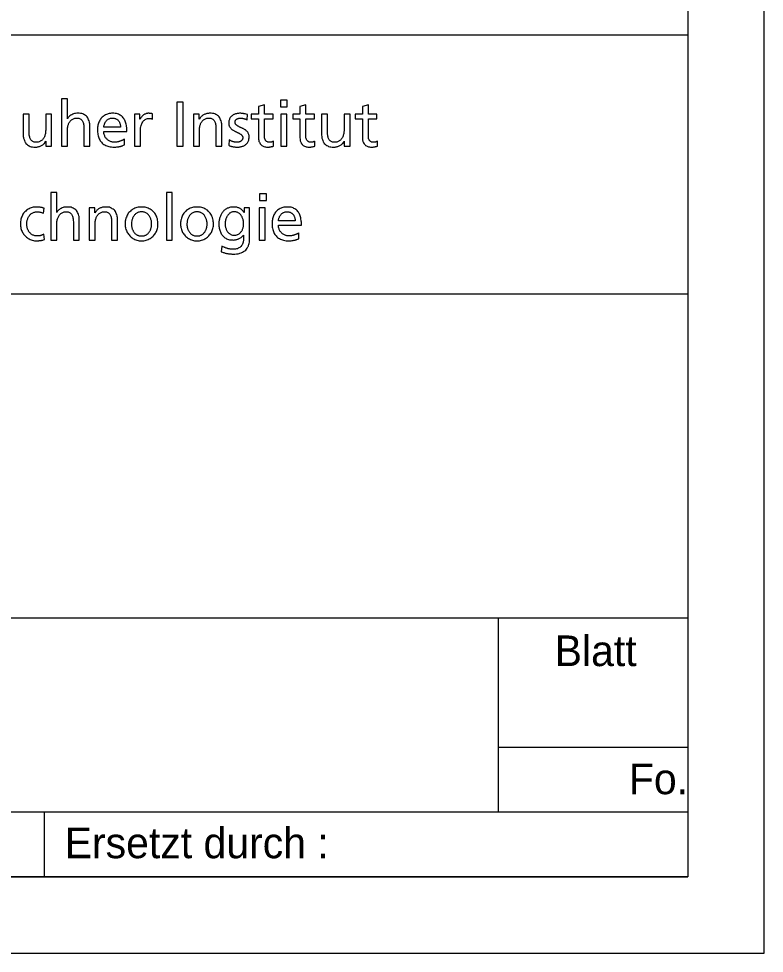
# Model space of a CAD drawing. Extents: x 0 to 297, y 0 to 210.
# Drawn here: x 272.66 to 297, y 0 to 30.52 of the extents above; entities that cross this region are included whole.
import ezdxf

# ---------------------------------------------------------------- set-up
doc = ezdxf.new("R2010")
doc.units = 0
doc.layers.add('90_Plankopf', color=7, linetype='Continuous')

msp = doc.modelspace()

# ---------------------------------------------------------------- linework, layer by layer
at = {"layer": '90_Plankopf'}
for p, q in [((294.5, 42.495), (294.5, 2.5)), ((205.56, 29.995), (294.5, 29.995)), ((205.56, 29.995), (294.5, 29.995)), ((294.5, 29.995), (294.5, 2.5)), ((277.028, 27.242), (277.028, 27.416)), ((280.116, 27.22), (280.133, 27.389)), ((275.986, 26.98), (275.441, 26.98)), ((275.441, 26.836), (276.193, 26.836)), ((276.112, 26.396), (276.112, 26.59)), ((279.536, 26.559), (279.526, 26.386)), ((280.981, 26.357), (280.981, 26.522)), ((282.333, 26.357), (282.333, 26.522)), ((284.372, 26.357), (284.372, 26.522)), ((273.476, 24.168), (273.492, 24.329)), ((281.686, 23.92), (281.142, 23.92)), ((281.142, 23.776), (281.893, 23.776)), ((281.812, 23.337), (281.812, 23.53)), ((273.5, 23.312), (273.486, 23.485)), ((279.298, 23.087), (279.277, 22.907)), ((252.501, 21.535), (294.5, 21.535)), ((252.501, 10.96), (294.5, 10.96)), ((288.324, 4.615), (288.324, 10.96)), ((288.324, 6.73), (294.5, 6.73)), ((252.501, 4.615), (294.5, 4.615)), ((273.5, 2.5), (273.5, 4.615)), ((294.5, 2.5), (205.56, 2.5)), ((211.4, 2.5), (294.5, 2.5)), ((211.4, 2.5), (294.5, 2.5))]:
    msp.add_line(p, q, dxfattribs=at)
for points in [[(0, 0), (297, 0), (297, 210), (0, 210)], [(12.5, 207.5), (294.5, 207.5), (294.5, 2.5), (12.5, 2.5)]]:
    msp.add_lwpolyline(points, close=True, dxfattribs=at)
for points in [[(274.255, 27.255), (274.251, 27.255), (274.251, 27.9), (274.057, 27.9), (274.057, 26.353), (274.251, 26.353), (274.251, 26.84)], [(277.823, 26.353), (278.029, 26.353), (278.029, 27.793), (277.823, 27.793), (277.823, 26.353)], [(281.427, 27.64), (281.427, 27.859), (281.208, 27.859), (281.208, 27.64), (281.427, 27.64)], [(280.686, 26.673), (280.686, 27.248), (280.964, 27.248), (280.964, 27.405), (280.686, 27.405), (280.686, 27.711), (280.492, 27.649), (280.492, 27.405), (280.254, 27.405), (280.254, 27.248), (280.492, 27.248), (280.492, 26.633)], [(282.038, 26.673), (282.038, 27.248), (282.316, 27.248), (282.316, 27.405), (282.038, 27.405), (282.038, 27.711), (281.844, 27.649), (281.844, 27.405), (281.606, 27.405), (281.606, 27.248), (281.844, 27.248), (281.844, 26.633)], [(284.077, 26.673), (284.077, 27.248), (284.355, 27.248), (284.355, 27.405), (284.077, 27.405), (284.077, 27.711), (283.883, 27.649), (283.883, 27.405), (283.646, 27.405), (283.646, 27.248), (283.883, 27.248), (283.883, 26.633)], [(273.002, 26.86), (273.002, 27.405), (272.808, 27.405), (272.808, 26.78)], [(273.547, 26.52), (273.551, 26.52), (273.551, 26.353), (273.739, 26.353), (273.739, 27.405), (273.545, 27.405), (273.545, 26.918)], [(276.626, 27.242), (276.622, 27.242), (276.622, 27.405), (276.44, 27.405), (276.44, 26.353), (276.634, 26.353), (276.634, 26.832)], [(278.558, 27.238), (278.554, 27.238), (278.554, 27.405), (278.366, 27.405), (278.366, 26.353), (278.56, 26.353), (278.56, 26.84)], [(281.22, 27.405), (281.22, 26.353), (281.414, 26.353), (281.414, 27.405), (281.22, 27.405)], [(282.742, 26.86), (282.742, 27.405), (282.548, 27.405), (282.548, 26.78)], [(283.286, 26.52), (283.29, 26.52), (283.29, 26.353), (283.478, 26.353), (283.478, 27.405), (283.284, 27.405), (283.284, 26.918)], [(274.793, 26.898), (274.793, 26.353), (274.987, 26.353), (274.987, 26.978)], [(279.103, 26.898), (279.103, 26.353), (279.297, 26.353), (279.297, 26.978)], [(273.909, 24.195), (273.905, 24.195), (273.905, 24.841), (273.711, 24.841), (273.711, 23.293), (273.905, 23.293), (273.905, 23.78)], [(277.482, 23.293), (277.676, 23.293), (277.676, 24.841), (277.482, 24.841), (277.482, 23.293)], [(280.747, 24.581), (280.747, 24.799), (280.528, 24.799), (280.528, 24.581), (280.747, 24.581)], [(275.152, 24.178), (275.147, 24.178), (275.147, 24.346), (274.96, 24.346), (274.96, 23.293), (275.154, 23.293), (275.154, 23.78)], [(280.198, 23.339), (280.198, 24.346), (280.018, 24.346), (280.018, 24.189), (280.014, 24.189)], [(280.515, 24.346), (280.515, 23.293), (280.709, 23.293), (280.709, 24.346), (280.515, 24.346)], [(274.448, 23.838), (274.448, 23.293), (274.642, 23.293), (274.642, 23.918)], [(275.696, 23.838), (275.696, 23.293), (275.89, 23.293), (275.89, 23.918)], [(280, 23.456), (280.004, 23.456), (280.004, 23.353)]]:
    msp.add_lwpolyline(points, dxfattribs=at)
for points in [[(274.251, 26.84), (274.251, 26.904), (274.257, 26.963), (274.27, 27.016), (274.282, 27.069), (274.302, 27.114), (274.328, 27.152), (274.354, 27.191), (274.387, 27.221), (274.427, 27.242), (274.468, 27.262), (274.515, 27.273), (274.571, 27.273), (274.627, 27.27), (274.671, 27.254), (274.704, 27.226), (274.736, 27.198), (274.759, 27.156), (274.773, 27.102), (274.787, 27.048), (274.794, 26.979), (274.793, 26.898)], [(274.987, 26.978), (274.988, 27.073), (274.974, 27.154), (274.946, 27.221), (274.918, 27.288), (274.874, 27.34), (274.816, 27.376), (274.758, 27.412), (274.684, 27.43), (274.593, 27.43), (274.519, 27.43), (274.454, 27.414), (274.395, 27.384), (274.337, 27.354), (274.291, 27.311), (274.255, 27.255)], [(276.193, 26.836), (276.193, 26.921), (276.185, 26.999), (276.17, 27.071), (276.154, 27.143), (276.128, 27.206), (276.092, 27.26), (276.056, 27.313), (276.009, 27.355), (275.949, 27.385), (275.889, 27.414), (275.816, 27.43), (275.728, 27.43), (275.654, 27.43), (275.586, 27.416), (275.526, 27.391), (275.466, 27.365), (275.414, 27.328), (275.37, 27.281), (275.327, 27.233), (275.294, 27.177), (275.271, 27.112), (275.247, 27.048), (275.236, 26.976), (275.235, 26.898), (275.235, 26.812), (275.246, 26.734), (275.268, 26.664), (275.289, 26.594), (275.323, 26.534), (275.368, 26.485), (275.412, 26.434), (275.469, 26.396), (275.537, 26.369), (275.606, 26.342), (275.687, 26.328), (275.78, 26.328), (275.837, 26.328), (275.886, 26.332), (275.927, 26.34), (275.967, 26.347), (276.002, 26.356), (276.032, 26.367), (276.061, 26.377), (276.088, 26.387), (276.112, 26.396)], [(275.441, 26.98), (275.445, 27.015), (275.453, 27.049), (275.465, 27.083), (275.477, 27.118), (275.494, 27.149), (275.517, 27.178), (275.54, 27.206), (275.568, 27.229), (275.602, 27.247), (275.636, 27.264), (275.677, 27.273), (275.724, 27.273), (275.766, 27.273), (275.803, 27.265), (275.836, 27.25), (275.868, 27.235), (275.895, 27.214), (275.918, 27.187), (275.94, 27.16), (275.957, 27.129), (275.969, 27.094), (275.98, 27.059), (275.986, 27.021), (275.986, 26.98)], [(277.028, 27.416), (277.015, 27.418), (277.002, 27.421), (276.99, 27.423), (276.978, 27.425), (276.964, 27.427), (276.95, 27.428), (276.936, 27.429), (276.919, 27.43), (276.901, 27.43), (276.863, 27.43), (276.827, 27.422), (276.791, 27.406), (276.756, 27.39), (276.724, 27.368), (276.696, 27.339), (276.667, 27.311), (276.644, 27.279), (276.626, 27.242)], [(276.634, 26.832), (276.635, 26.92), (276.647, 26.996), (276.67, 27.06), (276.694, 27.124), (276.727, 27.174), (276.77, 27.208), (276.812, 27.243), (276.863, 27.26), (276.921, 27.261), (276.938, 27.261), (276.956, 27.26), (276.974, 27.257), (276.993, 27.254), (277.011, 27.249), (277.028, 27.242)], [(279.297, 26.978), (279.297, 27.073), (279.283, 27.154), (279.255, 27.221), (279.227, 27.288), (279.184, 27.34), (279.126, 27.376), (279.068, 27.412), (278.993, 27.43), (278.902, 27.43), (278.853, 27.43), (278.806, 27.422), (278.761, 27.407), (278.716, 27.392), (278.676, 27.37), (278.64, 27.341), (278.605, 27.312), (278.577, 27.278), (278.558, 27.238)], [(278.56, 26.84), (278.56, 26.904), (278.566, 26.963), (278.579, 27.016), (278.592, 27.069), (278.611, 27.114), (278.637, 27.152), (278.663, 27.191), (278.696, 27.221), (278.737, 27.242), (278.777, 27.262), (278.825, 27.273), (278.88, 27.273), (278.936, 27.27), (278.98, 27.254), (279.013, 27.226), (279.046, 27.198), (279.069, 27.156), (279.082, 27.102), (279.097, 27.048), (279.103, 26.979), (279.103, 26.898)], [(280.133, 27.389), (280.095, 27.4), (280.056, 27.41), (280.017, 27.418), (279.978, 27.426), (279.936, 27.43), (279.891, 27.43), (279.839, 27.43), (279.79, 27.423), (279.745, 27.41), (279.7, 27.397), (279.661, 27.377), (279.627, 27.35), (279.594, 27.323), (279.567, 27.29), (279.549, 27.249), (279.53, 27.208), (279.52, 27.161), (279.52, 27.106), (279.52, 27.064), (279.529, 27.028), (279.545, 26.997), (279.561, 26.966), (279.583, 26.94), (279.61, 26.917), (279.637, 26.895), (279.667, 26.875), (279.699, 26.857), (279.732, 26.84), (279.764, 26.824), (279.796, 26.809), (279.829, 26.793), (279.858, 26.777), (279.885, 26.761), (279.912, 26.745), (279.934, 26.727), (279.951, 26.706), (279.967, 26.686), (279.975, 26.663), (279.976, 26.636), (279.975, 26.607), (279.969, 26.584), (279.957, 26.564), (279.945, 26.545), (279.93, 26.529), (279.91, 26.518), (279.89, 26.506), (279.869, 26.498), (279.846, 26.493), (279.823, 26.487), (279.8, 26.485), (279.778, 26.485), (279.758, 26.485), (279.735, 26.488), (279.707, 26.493), (279.679, 26.499), (279.65, 26.507), (279.62, 26.518), (279.59, 26.529), (279.562, 26.543), (279.536, 26.559)], [(279.526, 26.386), (279.571, 26.363), (279.617, 26.347), (279.667, 26.339), (279.715, 26.331), (279.765, 26.327), (279.815, 26.328), (279.862, 26.328), (279.908, 26.335), (279.951, 26.348), (279.995, 26.361), (280.034, 26.381), (280.069, 26.408), (280.103, 26.435), (280.131, 26.469), (280.151, 26.51), (280.171, 26.551), (280.182, 26.6), (280.182, 26.656), (280.182, 26.704), (280.173, 26.745), (280.157, 26.778), (280.14, 26.811), (280.119, 26.84), (280.092, 26.863), (280.065, 26.886), (280.035, 26.906), (280.003, 26.922), (279.97, 26.939), (279.938, 26.954), (279.906, 26.968), (279.873, 26.983), (279.843, 26.998), (279.817, 27.013), (279.789, 27.029), (279.768, 27.047), (279.751, 27.068), (279.735, 27.089), (279.726, 27.115), (279.726, 27.145), (279.726, 27.174), (279.735, 27.198), (279.752, 27.217), (279.769, 27.236), (279.792, 27.25), (279.82, 27.259), (279.847, 27.269), (279.878, 27.273), (279.912, 27.273), (279.923, 27.273), (279.939, 27.271), (279.957, 27.269), (279.975, 27.266), (279.994, 27.261), (280.015, 27.256), (280.035, 27.251), (280.054, 27.246), (280.072, 27.239), (280.09, 27.233), (280.105, 27.226), (280.116, 27.22)], [(273.545, 26.918), (273.545, 26.854), (273.539, 26.795), (273.526, 26.742), (273.513, 26.69), (273.494, 26.644), (273.468, 26.606), (273.441, 26.567), (273.408, 26.538), (273.368, 26.517), (273.328, 26.496), (273.28, 26.485), (273.225, 26.485), (273.169, 26.488), (273.124, 26.504), (273.092, 26.532), (273.059, 26.561), (273.036, 26.602), (273.022, 26.656), (273.008, 26.71), (273.002, 26.779), (273.002, 26.86)], [(283.284, 26.918), (283.284, 26.854), (283.278, 26.795), (283.265, 26.742), (283.253, 26.69), (283.233, 26.644), (283.207, 26.606), (283.181, 26.567), (283.148, 26.538), (283.107, 26.517), (283.067, 26.496), (283.019, 26.485), (282.964, 26.485), (282.908, 26.488), (282.864, 26.504), (282.831, 26.532), (282.799, 26.561), (282.776, 26.602), (282.762, 26.656), (282.748, 26.71), (282.741, 26.779), (282.742, 26.86)], [(272.808, 26.78), (272.808, 26.685), (272.822, 26.605), (272.85, 26.537), (272.878, 26.47), (272.921, 26.418), (272.979, 26.382), (273.037, 26.347), (273.112, 26.328), (273.202, 26.328), (273.251, 26.328), (273.299, 26.336), (273.344, 26.351), (273.389, 26.367), (273.429, 26.389), (273.464, 26.417), (273.5, 26.446), (273.527, 26.48), (273.547, 26.52)], [(276.112, 26.59), (276.1, 26.58), (276.083, 26.569), (276.059, 26.557), (276.036, 26.545), (276.01, 26.534), (275.98, 26.523), (275.95, 26.512), (275.919, 26.503), (275.886, 26.496), (275.853, 26.489), (275.82, 26.485), (275.788, 26.485), (275.742, 26.485), (275.698, 26.493), (275.656, 26.51), (275.615, 26.527), (275.578, 26.551), (275.546, 26.582), (275.514, 26.613), (275.488, 26.65), (275.47, 26.693), (275.451, 26.736), (275.442, 26.783), (275.441, 26.836)], [(280.492, 26.633), (280.492, 26.563), (280.505, 26.506), (280.531, 26.461), (280.557, 26.416), (280.595, 26.382), (280.643, 26.36), (280.691, 26.339), (280.749, 26.328), (280.816, 26.328), (280.847, 26.328), (280.877, 26.332), (280.905, 26.338), (280.934, 26.344), (280.959, 26.35), (280.981, 26.357)], [(280.981, 26.522), (280.966, 26.513), (280.948, 26.504), (280.926, 26.497), (280.904, 26.489), (280.879, 26.485), (280.849, 26.485), (280.819, 26.485), (280.792, 26.492), (280.767, 26.507), (280.743, 26.521), (280.723, 26.542), (280.708, 26.57), (280.694, 26.598), (280.686, 26.632), (280.686, 26.673)], [(281.844, 26.633), (281.844, 26.563), (281.857, 26.506), (281.883, 26.461), (281.909, 26.416), (281.947, 26.382), (281.995, 26.36), (282.043, 26.339), (282.101, 26.328), (282.168, 26.328), (282.199, 26.328), (282.229, 26.332), (282.257, 26.338), (282.286, 26.344), (282.311, 26.35), (282.333, 26.357)], [(282.333, 26.522), (282.318, 26.513), (282.3, 26.504), (282.278, 26.497), (282.256, 26.489), (282.231, 26.485), (282.201, 26.485), (282.171, 26.485), (282.144, 26.492), (282.119, 26.507), (282.095, 26.521), (282.075, 26.542), (282.06, 26.57), (282.046, 26.598), (282.038, 26.632), (282.038, 26.673)], [(282.548, 26.78), (282.548, 26.685), (282.561, 26.605), (282.589, 26.537), (282.617, 26.47), (282.66, 26.418), (282.719, 26.382), (282.777, 26.347), (282.851, 26.328), (282.942, 26.328), (282.991, 26.328), (283.038, 26.336), (283.083, 26.351), (283.128, 26.367), (283.169, 26.389), (283.204, 26.417), (283.239, 26.446), (283.267, 26.48), (283.286, 26.52)], [(283.883, 26.633), (283.883, 26.563), (283.896, 26.506), (283.922, 26.461), (283.949, 26.416), (283.986, 26.382), (284.034, 26.36), (284.082, 26.339), (284.14, 26.328), (284.207, 26.328), (284.238, 26.328), (284.268, 26.332), (284.296, 26.338), (284.325, 26.344), (284.35, 26.35), (284.372, 26.357)], [(284.372, 26.522), (284.357, 26.513), (284.339, 26.504), (284.318, 26.497), (284.296, 26.489), (284.27, 26.485), (284.24, 26.485), (284.21, 26.485), (284.183, 26.492), (284.158, 26.507), (284.134, 26.521), (284.114, 26.542), (284.1, 26.57), (284.085, 26.598), (284.077, 26.632), (284.077, 26.673)], [(273.492, 24.329), (273.473, 24.337), (273.451, 24.343), (273.424, 24.35), (273.397, 24.356), (273.369, 24.361), (273.34, 24.365), (273.311, 24.368), (273.283, 24.37), (273.257, 24.37), (273.176, 24.37), (273.103, 24.356), (273.037, 24.329), (272.972, 24.302), (272.915, 24.264), (272.868, 24.215), (272.821, 24.166), (272.784, 24.108), (272.759, 24.041), (272.734, 23.973), (272.721, 23.9), (272.72, 23.819), (272.721, 23.744), (272.734, 23.673), (272.76, 23.606), (272.785, 23.54), (272.822, 23.482), (272.87, 23.431), (272.917, 23.381), (272.974, 23.341), (273.039, 23.312), (273.105, 23.284), (273.177, 23.269), (273.257, 23.268), (273.281, 23.268), (273.306, 23.269), (273.333, 23.272), (273.361, 23.274), (273.389, 23.278), (273.417, 23.284), (273.446, 23.29), (273.473, 23.299), (273.5, 23.312)], [(273.486, 23.485), (273.466, 23.472), (273.444, 23.461), (273.42, 23.452), (273.396, 23.443), (273.372, 23.437), (273.348, 23.432), (273.323, 23.428), (273.3, 23.425), (273.277, 23.425), (273.228, 23.426), (273.184, 23.433), (273.145, 23.448), (273.107, 23.463), (273.074, 23.484), (273.046, 23.51), (273.018, 23.536), (272.996, 23.566), (272.978, 23.6), (272.961, 23.633), (272.948, 23.669), (272.939, 23.706), (272.931, 23.744), (272.927, 23.782), (272.927, 23.819), (272.927, 23.87), (272.934, 23.919), (272.949, 23.965), (272.964, 24.012), (272.986, 24.054), (273.015, 24.091), (273.044, 24.129), (273.079, 24.158), (273.121, 24.18), (273.163, 24.202), (273.211, 24.213), (273.265, 24.213), (273.297, 24.213), (273.33, 24.21), (273.366, 24.202), (273.402, 24.195), (273.438, 24.184), (273.476, 24.168)], [(273.905, 23.78), (273.905, 23.845), (273.911, 23.903), (273.924, 23.956), (273.937, 24.009), (273.956, 24.054), (273.982, 24.093), (274.008, 24.131), (274.042, 24.161), (274.082, 24.182), (274.122, 24.203), (274.17, 24.213), (274.225, 24.213), (274.281, 24.21), (274.325, 24.195), (274.358, 24.166), (274.391, 24.138), (274.414, 24.097), (274.428, 24.042), (274.442, 23.988), (274.448, 23.92), (274.448, 23.838)], [(274.642, 23.918), (274.642, 24.013), (274.628, 24.094), (274.6, 24.161), (274.572, 24.229), (274.529, 24.28), (274.471, 24.316), (274.413, 24.352), (274.338, 24.37), (274.248, 24.37), (274.174, 24.37), (274.108, 24.355), (274.05, 24.325), (273.992, 24.294), (273.945, 24.251), (273.909, 24.195)], [(275.89, 23.918), (275.891, 24.013), (275.877, 24.094), (275.849, 24.161), (275.821, 24.229), (275.777, 24.28), (275.719, 24.316), (275.661, 24.352), (275.587, 24.37), (275.496, 24.37), (275.447, 24.37), (275.4, 24.362), (275.355, 24.347), (275.31, 24.332), (275.269, 24.31), (275.234, 24.281), (275.199, 24.253), (275.171, 24.219), (275.152, 24.178)], [(275.154, 23.78), (275.154, 23.845), (275.16, 23.903), (275.173, 23.956), (275.185, 24.009), (275.205, 24.054), (275.231, 24.093), (275.257, 24.131), (275.29, 24.161), (275.33, 24.182), (275.371, 24.203), (275.418, 24.213), (275.474, 24.213), (275.53, 24.21), (275.574, 24.195), (275.607, 24.166), (275.639, 24.138), (275.662, 24.097), (275.676, 24.042), (275.69, 23.988), (275.697, 23.92), (275.696, 23.838)], [(277.197, 23.945), (277.191, 23.978), (277.182, 24.01), (277.171, 24.041), (277.145, 24.108), (277.109, 24.166), (277.062, 24.215), (277.015, 24.264), (276.958, 24.302), (276.893, 24.329), (276.828, 24.356), (276.755, 24.37), (276.675, 24.37), (276.594, 24.37), (276.521, 24.356), (276.455, 24.329), (276.389, 24.302), (276.333, 24.264), (276.286, 24.215), (276.239, 24.166), (276.202, 24.108), (276.177, 24.041), (276.151, 23.973), (276.139, 23.9), (276.138, 23.819)], [(276.344, 23.819), (276.344, 23.87), (276.352, 23.919), (276.367, 23.965), (276.382, 24.012), (276.403, 24.054), (276.432, 24.091), (276.46, 24.129), (276.494, 24.158), (276.535, 24.18), (276.576, 24.202), (276.622, 24.213), (276.675, 24.213), (276.726, 24.213), (276.772, 24.202), (276.813, 24.18), (276.853, 24.158), (276.888, 24.129), (276.916, 24.091), (276.944, 24.054), (276.966, 24.012), (276.98, 23.965), (276.995, 23.919), (277.003, 23.87), (277.003, 23.819), (277.003, 23.782), (276.999, 23.744), (276.99, 23.706), (276.982, 23.669), (276.97, 23.633), (276.952, 23.6), (276.936, 23.566), (276.914, 23.536), (276.888, 23.51), (276.862, 23.484), (276.832, 23.463), (276.796, 23.448), (276.761, 23.433), (276.72, 23.426), (276.675, 23.425), (276.629, 23.426), (276.588, 23.433), (276.552, 23.448), (276.517, 23.463), (276.486, 23.484), (276.459, 23.51), (276.433, 23.536), (276.412, 23.566), (276.395, 23.6), (276.378, 23.633), (276.365, 23.669), (276.357, 23.706), (276.349, 23.744), (276.344, 23.782), (276.344, 23.819)], [(279.007, 23.945), (279.001, 23.978), (278.992, 24.01), (278.981, 24.041), (278.955, 24.108), (278.919, 24.166), (278.872, 24.215), (278.825, 24.264), (278.768, 24.302), (278.703, 24.329), (278.638, 24.356), (278.565, 24.37), (278.485, 24.37), (278.404, 24.37), (278.331, 24.356), (278.265, 24.329), (278.199, 24.302), (278.143, 24.264), (278.096, 24.215), (278.049, 24.166), (278.012, 24.108), (277.987, 24.041), (277.961, 23.973), (277.949, 23.9), (277.948, 23.819)], [(278.155, 23.819), (278.155, 23.87), (278.162, 23.919), (278.177, 23.965), (278.192, 24.012), (278.213, 24.054), (278.242, 24.091), (278.27, 24.129), (278.305, 24.158), (278.345, 24.18), (278.386, 24.202), (278.432, 24.213), (278.485, 24.213), (278.536, 24.213), (278.582, 24.202), (278.623, 24.18), (278.663, 24.158), (278.698, 24.129), (278.726, 24.091), (278.754, 24.054), (278.776, 24.012), (278.79, 23.965), (278.805, 23.919), (278.813, 23.87), (278.813, 23.819), (278.813, 23.782), (278.809, 23.744), (278.8, 23.706), (278.792, 23.669), (278.78, 23.633), (278.763, 23.6), (278.746, 23.566), (278.724, 23.536), (278.698, 23.51), (278.672, 23.484), (278.642, 23.463), (278.606, 23.448), (278.571, 23.433), (278.53, 23.426), (278.485, 23.425), (278.439, 23.426), (278.398, 23.433), (278.362, 23.448), (278.327, 23.463), (278.296, 23.484), (278.269, 23.51), (278.243, 23.536), (278.222, 23.566), (278.205, 23.6), (278.188, 23.633), (278.175, 23.669), (278.167, 23.706), (278.159, 23.744), (278.155, 23.782), (278.155, 23.819)], [(280.014, 24.189), (279.995, 24.227), (279.97, 24.259), (279.94, 24.286), (279.909, 24.313), (279.871, 24.334), (279.827, 24.348), (279.782, 24.363), (279.729, 24.37), (279.667, 24.37), (279.604, 24.37), (279.547, 24.359), (279.496, 24.338), (279.446, 24.317), (279.402, 24.288), (279.364, 24.251), (279.327, 24.215), (279.296, 24.172), (279.271, 24.125), (279.246, 24.077), (279.227, 24.027), (279.215, 23.973), (279.203, 23.919), (279.197, 23.866), (279.197, 23.811), (279.197, 23.742), (279.206, 23.677), (279.225, 23.615), (279.243, 23.554), (279.272, 23.498), (279.309, 23.45), (279.346, 23.402), (279.393, 23.364), (279.449, 23.336), (279.506, 23.308), (279.571, 23.294), (279.647, 23.293), (279.692, 23.293), (279.736, 23.299), (279.779, 23.311), (279.823, 23.323), (279.863, 23.341), (279.901, 23.365), (279.939, 23.39), (279.972, 23.42), (280, 23.456)], [(279.696, 23.45), (279.651, 23.45), (279.61, 23.46), (279.574, 23.48), (279.538, 23.5), (279.507, 23.527), (279.482, 23.561), (279.456, 23.596), (279.437, 23.635), (279.423, 23.68), (279.41, 23.724), (279.403, 23.772), (279.403, 23.821), (279.403, 23.857), (279.407, 23.894), (279.415, 23.931), (279.422, 23.968), (279.434, 24.003), (279.45, 24.037), (279.465, 24.071), (279.485, 24.101), (279.508, 24.127), (279.532, 24.154), (279.559, 24.175), (279.591, 24.19), (279.622, 24.205), (279.657, 24.213), (279.696, 24.213), (279.748, 24.213), (279.793, 24.202), (279.831, 24.181), (279.87, 24.16), (279.902, 24.13), (279.927, 24.092), (279.953, 24.055), (279.972, 24.012), (279.985, 23.963), (279.997, 23.914), (280.004, 23.862), (280.004, 23.807), (280.004, 23.758), (279.996, 23.711), (279.981, 23.668), (279.966, 23.625), (279.945, 23.587), (279.918, 23.555), (279.891, 23.522), (279.859, 23.497), (279.821, 23.478), (279.783, 23.46), (279.742, 23.45), (279.696, 23.45)], [(281.893, 23.776), (281.893, 23.861), (281.885, 23.94), (281.87, 24.012), (281.854, 24.084), (281.828, 24.146), (281.792, 24.2), (281.756, 24.254), (281.709, 24.295), (281.649, 24.325), (281.589, 24.355), (281.516, 24.37), (281.428, 24.37), (281.354, 24.37), (281.286, 24.357), (281.226, 24.331), (281.166, 24.305), (281.114, 24.269), (281.07, 24.221), (281.027, 24.174), (280.994, 24.118), (280.971, 24.052), (280.947, 23.988), (280.936, 23.916), (280.935, 23.838), (280.935, 23.752), (280.946, 23.674), (280.968, 23.604), (280.99, 23.535), (281.023, 23.475), (281.068, 23.425), (281.112, 23.375), (281.169, 23.336), (281.237, 23.309), (281.306, 23.282), (281.387, 23.269), (281.48, 23.268), (281.537, 23.269), (281.586, 23.273), (281.627, 23.28), (281.667, 23.288), (281.702, 23.297), (281.732, 23.307), (281.761, 23.317), (281.788, 23.327), (281.812, 23.337)], [(281.142, 23.92), (281.145, 23.955), (281.153, 23.989), (281.165, 24.024), (281.177, 24.058), (281.195, 24.089), (281.217, 24.118), (281.24, 24.147), (281.268, 24.17), (281.302, 24.187), (281.336, 24.204), (281.377, 24.213), (281.424, 24.213), (281.466, 24.213), (281.503, 24.206), (281.536, 24.19), (281.568, 24.175), (281.596, 24.154), (281.618, 24.127), (281.64, 24.101), (281.657, 24.069), (281.669, 24.034), (281.68, 23.999), (281.686, 23.961), (281.686, 23.92)], [(276.138, 23.819), (276.139, 23.744), (276.152, 23.673), (276.177, 23.606), (276.203, 23.54), (276.24, 23.482), (276.287, 23.431), (276.335, 23.381), (276.391, 23.341), (276.457, 23.312), (276.522, 23.284), (276.595, 23.269), (276.675, 23.268), (276.754, 23.269), (276.826, 23.284), (276.891, 23.312), (276.957, 23.341), (277.013, 23.381), (277.06, 23.431), (277.108, 23.482), (277.144, 23.54), (277.17, 23.606), (277.196, 23.673), (277.209, 23.744), (277.209, 23.819), (277.209, 23.863), (277.205, 23.905), (277.197, 23.945)], [(277.948, 23.819), (277.949, 23.744), (277.962, 23.673), (277.987, 23.606), (278.013, 23.54), (278.05, 23.482), (278.097, 23.431), (278.145, 23.381), (278.201, 23.341), (278.267, 23.312), (278.332, 23.284), (278.405, 23.269), (278.485, 23.268), (278.564, 23.269), (278.636, 23.284), (278.701, 23.312), (278.767, 23.341), (278.823, 23.381), (278.87, 23.431), (278.918, 23.482), (278.954, 23.54), (278.98, 23.606), (279.006, 23.673), (279.019, 23.744), (279.019, 23.819), (279.019, 23.863), (279.015, 23.905), (279.007, 23.945)], [(281.812, 23.53), (281.8, 23.521), (281.783, 23.51), (281.76, 23.497), (281.737, 23.485), (281.71, 23.474), (281.68, 23.463), (281.651, 23.452), (281.619, 23.443), (281.586, 23.436), (281.553, 23.429), (281.521, 23.426), (281.488, 23.425), (281.442, 23.426), (281.398, 23.434), (281.357, 23.451), (281.315, 23.468), (281.278, 23.492), (281.246, 23.523), (281.214, 23.554), (281.188, 23.59), (281.17, 23.633), (281.152, 23.676), (281.142, 23.724), (281.142, 23.776)], [(279.277, 22.907), (279.333, 22.888), (279.383, 22.873), (279.426, 22.863), (279.468, 22.852), (279.508, 22.845), (279.545, 22.841), (279.582, 22.837), (279.618, 22.835), (279.655, 22.835), (279.78, 22.835), (279.883, 22.855), (279.963, 22.895), (280.044, 22.934), (280.103, 22.991), (280.141, 23.066), (280.179, 23.141), (280.198, 23.232), (280.198, 23.339)], [(280.004, 23.353), (280.003, 23.279), (279.991, 23.214), (279.965, 23.16), (279.939, 23.106), (279.902, 23.065), (279.853, 23.036), (279.804, 23.007), (279.746, 22.992), (279.678, 22.992), (279.642, 22.992), (279.61, 22.994), (279.579, 22.997), (279.549, 23), (279.519, 23.006), (279.49, 23.014), (279.461, 23.021), (279.431, 23.031), (279.4, 23.043), (279.369, 23.055), (279.335, 23.07), (279.298, 23.087)]]:
    msp.add_open_spline(points, degree=3, dxfattribs=at)

# ---------------------------------------------------------------- texts
for s, p in [('Blatt', (290.157, 9.379)), ('Fo.', (292.58, 5.196)), ('Ersetzt durch :', (274.163, 3.105))]:
    msp.add_text(s, height=1, dxfattribs=at).set_placement(p)

doc.saveas('drawing.dxf')
